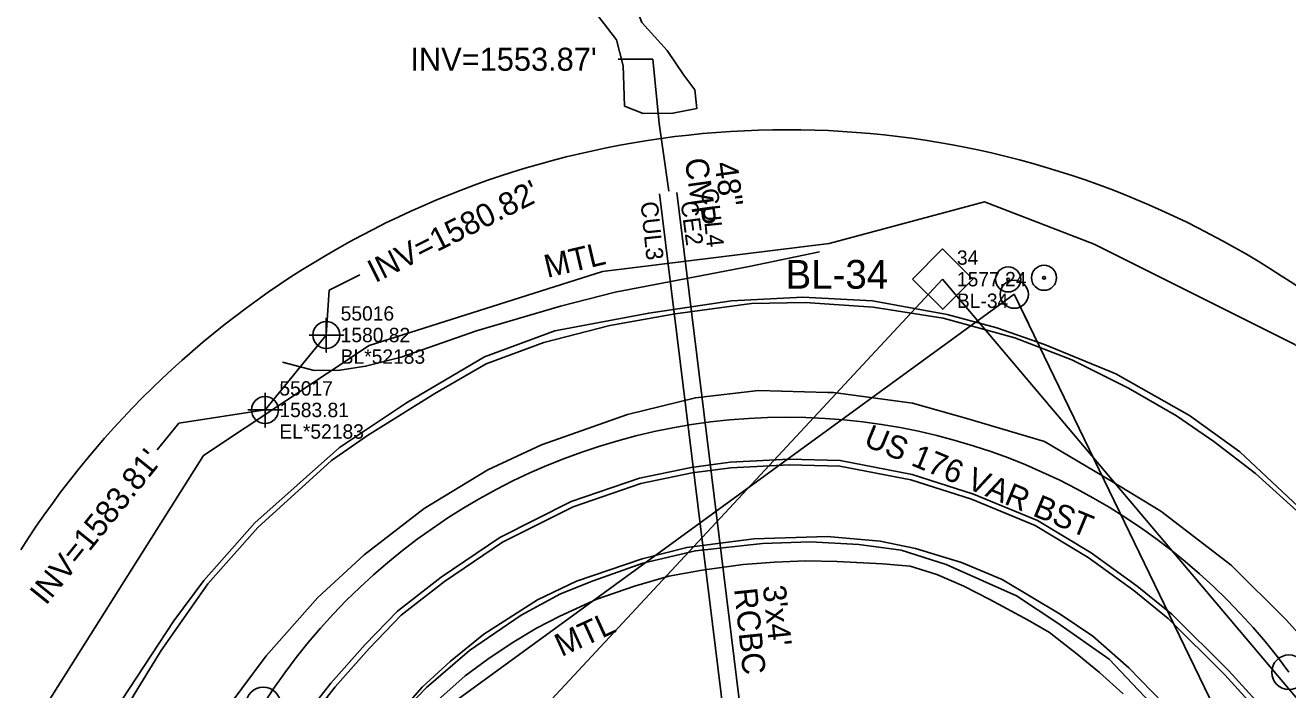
# Model space of a CAD drawing. Extents: x 1004911 to 1009660, y 551419 to 554278.
# Drawn here: x 1007382.7 to 1007602.2, y 552166.7 to 552282.2 of the extents above; entities that cross this region are included whole.
import ezdxf

# ---------------------------------------------------------------- set-up
doc = ezdxf.new("R2010")
doc.units = 0
for name, color, linetype in [('COGO Default Chain', 7, 'Continuous'), ('CTL Secondary Horizontal and Vertical CELL', 7, 'Continuous'), ('CTL Secondary Horizontal and Vertical Cogo Comment', 7, 'Continuous'), ('CTL Secondary Horizontal and Vertical Cogo Elevation', 7, 'Continuous'), ('CTL Secondary Horizontal and Vertical Cogo Number', 7, 'Continuous'), ('CTL Secondary Horizontal and Vertical Text', 7, 'Continuous'), ('Default', 7, 'Continuous'), ('Exist Guardrail Text', 7, 'Continuous'), ('Exist Horizontal Alignment', 7, 'Continuous'), ('Exist Horizontal Alignment Point', 7, 'Continuous'), ('Exist Hydro Jurisdictional Stream or Body of Water', 7, 'Continuous'), ('Exist Right of Way Line', 7, 'Continuous'), ('Exist Roads EOP Text', 7, 'Continuous'), ('Exist Roads EOT', 7, 'Continuous'), ('Exist Roads Soil', 7, 'Continuous'), ('Exist Structure Major Deck Tunnel Box Culvert Table CELL', 7, 'Continuous'), ('Exist Structure Major Deck Tunnel Box Culvert Text', 7, 'Continuous'), ('Exist Structure Minor Pipes CMP 18 Inch', 7, 'Continuous'), ('Exist Structure Minor Pipes CMP 18 Inch Cogo Comment', 7, 'Continuous'), ('Exist Structure Minor Pipes CMP 18 Inch Cogo Elevation', 7, 'Continuous'), ('Exist Structure Minor Pipes CMP 18 Inch Cogo Number', 7, 'Continuous'), ('Exist Structure Minor Pipes CMP 18 Inch Cogo Point CELL', 7, 'Continuous'), ('Exist Structure Minor Pipes CMP 18 Inch Invert', 7, 'Continuous'), ('Exist Structure Minor Pipes CMP 18 Inch Leader', 7, 'Continuous'), ('Exist Structure Minor Pipes CMP 48 Inch', 7, 'Continuous'), ('Exist Structure Minor Pipes CMP 48 Inch Invert', 7, 'Continuous'), ('Exist Structure Minor Pipes CMP 48 Inch Leader', 7, 'Continuous'), ('Exist Structure Minor Pipes CMP 48 Inch Text', 7, 'Continuous'), ('Prop Grid Mask', 7, 'Continuous'), ('Sheet Plan Layout CELL', 7, 'Continuous'), ('Sheet Plot Border Inside CELL', 7, 'Continuous')]:
    doc.layers.add(name, color=color, linetype=linetype)

msp = doc.modelspace()

# ---------------------------------------------------------------- linework, layer by layer
at = {"layer": 'COGO Default Chain'}
for p, q in [((1007359.18, 552041.29), (1007542.18, 552238.06)), ((1007542.18, 552238.06), (1007776.37, 551961.08))]:
    msp.add_line(p, q, dxfattribs=at)
at = {"layer": 'CTL Secondary Horizontal and Vertical CELL'}
msp.add_line((1007542.18, 552238.06), (1007542.18, 552238.06), dxfattribs=at)
msp.add_lwpolyline([(1007536.96, 552238.08), (1007542.2, 552243.32), (1007547.45, 552238.07), (1007542.21, 552232.83)], close=True, dxfattribs=at)
at = {"layer": 'Default'}
msp.add_lwpolyline([(1005524.55, 552120.23), (1005736, 552138.07), (1005876.82, 552290.73), (1006051.03, 552232.37), (1006285.21, 552359.76), (1006537.01, 552607.23), (1006619.79, 552246.45), (1006777.44, 552223.19), (1007040.23, 552379.15), (1007196.11, 552162.94), (1007285.57, 552039.61), (1007554.65, 552235.44), (1007625.93, 552087.97), (1007798.71, 551946.8), (1008114.55, 551869.88), (1008306.5, 551776.16), (1008516.03, 551764.25), (1008753.59, 551928.05), (1008927.98, 552049.02)], dxfattribs=at)
at = {"layer": 'Exist Horizontal Alignment'}
msp.add_arc((1007515.15, 552106.05), 108, 36.1169, 147.4703, dxfattribs=at)
at = {"layer": 'Exist Horizontal Alignment Point'}
msp.add_line((1007599.97, 552167.94), (1007599.97, 552167.94), dxfattribs=at)
for centre in [(1007602.4, 552169.71), (1007424.1, 552164.12)]:
    msp.add_circle(centre, 3, dxfattribs=at)
at = {"layer": 'Exist Hydro Jurisdictional Stream or Body of Water'}
for q in [(1007557.12, 552230.38), (1007554.65, 552235.44)]:
    msp.add_line((1007554.65, 552235.44), q, dxfattribs=at)
msp.add_lwpolyline([(1007473.32, 552313.51), (1007473.47, 552304.27), (1007474.76, 552295.25), (1007477.98, 552290.52), (1007482.38, 552283.75), (1007485.5, 552279.67), (1007486.68, 552275.16), (1007486.79, 552271.72), (1007486.9, 552268.17), (1007490.12, 552266.89), (1007495.32, 552266.91), (1007499.47, 552267.74), (1007499.14, 552270.97), (1007497.21, 552273.55), (1007494.31, 552277.84), (1007489.9, 552282.68), (1007487.22, 552289.66), (1007484.75, 552294.49), (1007482.6, 552299.65), (1007482.49, 552305.02), (1007481.29, 552315)], dxfattribs=at)
msp.add_circle((1007554.65, 552235.44), 2.45, dxfattribs=at)
at = {"layer": 'Exist Right of Way Line'}
msp.add_arc((1007515.15, 552106.05), 158, 36.1169, 147.4703, dxfattribs=at)
at = {"layer": 'Exist Roads EOT'}
for points in [[(1007604.41, 552197.18), (1007596.57, 552204.24), (1007589.34, 552209.81), (1007582.84, 552214.31), (1007574.51, 552219.09), (1007564.67, 552224.04), (1007554.72, 552227.88), (1007542.27, 552231.27), (1007530.1, 552233.22), (1007518.32, 552234), (1007508.98, 552233.83), (1007495.7, 552232.05), (1007484.36, 552229.99), (1007472.85, 552227.05), (1007462.85, 552223.32), (1007453.9, 552218.2), (1007442.23, 552210.86), (1007435.95, 552206.52), (1007423.17, 552194.85), (1007414.44, 552185.11), (1007406.33, 552173.49), (1007401.66, 552165.81), (1007387.21, 552140.79), (1007379.71, 552129.5)], [(1007608.92, 552171.03), (1007601.91, 552178.81), (1007592.38, 552188.35), (1007580.13, 552197.7), (1007571.57, 552202.95), (1007559.9, 552209.86), (1007546.38, 552213.85), (1007536.94, 552216.48), (1007523.23, 552218.33), (1007522.16, 552218.33), (1007510.2, 552218.72), (1007499.21, 552217.45), (1007487.44, 552214.53), (1007472.46, 552209.28), (1007463.12, 552204.9), (1007452.04, 552198.18), (1007441.63, 552190.1), (1007433.56, 552182.71), (1007424.61, 552172.59), (1007416.15, 552161.2)], [(1007430.81, 552161.38), (1007435.87, 552167.78), (1007441.81, 552174.51), (1007447.43, 552180.35), (1007455.04, 552186.24), (1007465.21, 552193.14), (1007477.61, 552199.37), (1007489.5, 552203.48), (1007498.5, 552205.32), (1007505.28, 552206.21), (1007515.51, 552206.76), (1007524.4, 552206.54), (1007536.91, 552204.09), (1007547.58, 552200.7), (1007558.69, 552196.09), (1007568.03, 552190.47), (1007576.03, 552184.69), (1007582.04, 552179.79), (1007591.93, 552169.95), (1007600.77, 552160.27)], [(1007431.59, 552160.8), (1007436.61, 552167.16), (1007442.53, 552173.85), (1007448.08, 552179.62), (1007455.61, 552185.46), (1007465.7, 552192.3), (1007477.98, 552198.47), (1007489.76, 552202.55), (1007498.66, 552204.36), (1007505.37, 552205.24), (1007515.52, 552205.79), (1007524.3, 552205.57), (1007536.67, 552203.15), (1007547.24, 552199.79), (1007558.26, 552195.22), (1007567.5, 552189.66), (1007575.44, 552183.92), (1007581.39, 552179.07), (1007591.23, 552169.28), (1007600.02, 552159.65)], [(1007443.4, 552157.58), (1007451.73, 552167.09), (1007456.57, 552171.6), (1007462.46, 552176.33), (1007471.74, 552182.28), (1007478.52, 552185.56), (1007489.97, 552189.45), (1007497.7, 552191.4), (1007509.37, 552192.9), (1007522.1, 552193.29), (1007531.32, 552192.51), (1007537.49, 552191.23), (1007545.49, 552188.78), (1007552.55, 552185.84), (1007562.61, 552179.83), (1007568.28, 552175.99), (1007574.56, 552170.49), (1007580.67, 552164.2)]]:
    msp.add_lwpolyline(points, dxfattribs=at)
for centre, radius in [((1007553.59, 552238.02), 2.18), ((1007559.82, 552238.3), 2.18), ((1007553.59, 552238.02), 0.24), ((1007559.82, 552238.3), 0.24)]:
    msp.add_circle(centre, radius, dxfattribs=at)
at = {"layer": 'Exist Roads Soil'}
for p, q in [((1007505.32, 552152.68), (1007492.98, 552252.9)), ((1007508.28, 552153.01), (1007495.97, 552253.15))]:
    msp.add_line(p, q, dxfattribs=at)
at = {"layer": 'Exist Structure Minor Pipes CMP 18 Inch'}
msp.add_line((1007435.05, 552228.35), (1007424.4, 552215.32), dxfattribs=at)
at = {"layer": 'Exist Structure Minor Pipes CMP 18 Inch Cogo Point CELL'}
for points in [[(1007435.05, 552231.35), (1007435.05, 552225.35), (1007435.05, 552228.35), (1007438.05, 552228.35), (1007432.05, 552228.35)], [(1007424.4, 552218.32), (1007424.4, 552212.32), (1007424.4, 552215.32), (1007427.4, 552215.32), (1007421.4, 552215.32)]]:
    msp.add_lwpolyline(points, dxfattribs=at)
for centre in [(1007435.05, 552228.35), (1007424.4, 552215.32)]:
    msp.add_circle(centre, 2.34, dxfattribs=at)
at = {"layer": 'Exist Structure Minor Pipes CMP 18 Inch Leader'}
for points in [[(1007435.05, 552228.35), (1007435.55, 552236.12), (1007440.91, 552238.82)], [(1007424.4, 552215.32), (1007409.44, 552213.03), (1007405.67, 552208.36)]]:
    msp.add_lwpolyline(points, dxfattribs=at)
at = {"layer": 'Exist Structure Minor Pipes CMP 48 Inch'}
msp.add_line((1007494.57, 552253.38), (1007492.92, 552265.15), dxfattribs=at)
at = {"layer": 'Exist Structure Minor Pipes CMP 48 Inch Leader'}
msp.add_lwpolyline([(1007492.92, 552265.15), (1007491.81, 552276.3), (1007485.81, 552276.3)], dxfattribs=at)
at = {"layer": 'Prop Grid Mask'}
for points in [[(1007427.42, 552223.6), (1007432.93, 552222.15), (1007437.43, 552222.26), (1007441.87, 552222.93), (1007448.04, 552224.49), (1007461.16, 552229.1), (1007475.78, 552233.39), (1007485.28, 552235.78), (1007508.57, 552240.28), (1007520.79, 552242.79)], [(1007573.59, 552165.94), (1007569.45, 552169.64), (1007565.57, 552172.85), (1007560.76, 552176.6), (1007557.05, 552178.77), (1007550.41, 552182.37), (1007545.86, 552184.68), (1007541.16, 552186.71), (1007536.53, 552188.15), (1007531.77, 552188.56), (1007523.84, 552188.96), (1007518.33, 552189.11), (1007512.99, 552188.87), (1007507.53, 552188.45), (1007500.41, 552187.44), (1007494.61, 552186.4), (1007488.64, 552184.69), (1007482.1, 552182.39), (1007475.64, 552179.48), (1007471.58, 552177.38), (1007467.37, 552174.82), (1007463.16, 552171.98), (1007459.22, 552169.08), (1007454.43, 552164.85)]]:
    msp.add_lwpolyline(points, dxfattribs=at)
at = {"layer": 'Sheet Plan Layout CELL'}
for points in [[(1007604.06, 552198.45), (1007593.88, 552208.01), (1007585.11, 552214.36), (1007572.29, 552221.57), (1007559.88, 552226.69), (1007551.62, 552229.58), (1007542.96, 552231.89), (1007529.98, 552234.31), (1007517.88, 552234.91), (1007505.5, 552234.31), (1007491.12, 552232.15), (1007474.81, 552229.1), (1007462.54, 552224.57), (1007448.98, 552216.57), (1007437.32, 552208.79), (1007422.65, 552195.67), (1007413.76, 552185.66), (1007408.54, 552178.66), (1007396.93, 552160.92), (1007385.26, 552139.47), (1007378.38, 552129.07)], [(1007448.06, 552162.45), (1007452.49, 552167.06), (1007459.93, 552173.48), (1007468.92, 552179.62), (1007475.76, 552183.32), (1007481.44, 552185.59), (1007490.06, 552188.67), (1007499.22, 552190.83), (1007510.86, 552192.12), (1007519.21, 552192.41), (1007527.64, 552191.9), (1007535, 552190.94), (1007542.82, 552188.44), (1007555.05, 552183.01), (1007562.07, 552178.35), (1007571.16, 552171.97), (1007580.3, 552162.32)]]:
    msp.add_lwpolyline(points, dxfattribs=at)
at = {"layer": 'Sheet Plot Border Inside CELL'}
msp.add_lwpolyline([(1008018.93, 551905.44), (1007985.96, 551910.69), (1007970.5, 551948.55), (1007944.43, 551944.76), (1007935.18, 551975.26), (1007927.71, 551982.4), (1007894.05, 551968.8), (1007853.66, 551980.36), (1007841.09, 551991.4), (1007816.34, 552003.15), (1007758.29, 552047.11), (1007642.78, 552183.47), (1007603.4, 552226.7), (1007568.56, 552244.13), (1007549.47, 552251.53), (1007522.45, 552244.25), (1007483.06, 552239.39), (1007442.5, 552226.54), (1007413.71, 552207.37), (1007375.88, 552147.49)], dxfattribs=at)

# ---------------------------------------------------------------- texts
at = {"layer": 'CTL Secondary Horizontal and Vertical Cogo Comment'}
msp.add_text('BL-34', height=2.5, dxfattribs=at).set_placement((1007544.68, 552233.06))
at = {"layer": 'CTL Secondary Horizontal and Vertical Cogo Elevation'}
msp.add_text('1577.24', height=2.5, dxfattribs=at).set_placement((1007544.68, 552236.81))
at = {"layer": 'CTL Secondary Horizontal and Vertical Cogo Number'}
msp.add_text('34', height=2.5, dxfattribs=at).set_placement((1007544.68, 552240.56))
at = {"layer": 'CTL Secondary Horizontal and Vertical Text'}
msp.add_text('BL-34', height=5, dxfattribs=at).set_placement((1007514.88, 552236.4))
at = {"layer": 'Exist Guardrail Text'}
for rotation, p in [(13.3119, (1007473.46, 552238.26)), (24.6254, (1007475.94, 552172.34))]:
    msp.add_text('MTL', height=4, rotation=rotation, dxfattribs=at).set_placement(p)
at = {"layer": 'Exist Roads EOP Text'}
msp.add_text('US 176 VAR BST ', height=4, rotation=337.464, dxfattribs=at).set_placement((1007528.27, 552209.19))
at = {"layer": 'Exist Structure Major Deck Tunnel Box Culvert Table CELL'}
for s, rotation, p in [('CUL4', 275.984, (1007500.17, 552253.71)), ('CUL3', 275.984, (1007489.67, 552251.43)), ('CE2', 277.5358, (1007496.63, 552251.48))]:
    msp.add_text(s, height=3, rotation=rotation, dxfattribs=at).set_placement(p)
at = {"layer": 'Exist Structure Major Deck Tunnel Box Culvert Text'}
for s, p in [('RCBC', (1007505.94, 552184.19)), ("3'x4'", (1007510.92, 552184.67))]:
    msp.add_text(s, height=4, rotation=275.9227, dxfattribs=at).set_placement(p)
at = {"layer": 'Exist Structure Minor Pipes CMP 18 Inch Cogo Comment'}
for s, p in [('BL*52183', (1007437.55, 552223.35)), ('EL*52183', (1007426.9, 552210.32))]:
    msp.add_text(s, height=2.5, dxfattribs=at).set_placement(p)
at = {"layer": 'Exist Structure Minor Pipes CMP 18 Inch Cogo Elevation'}
for s, p in [('1580.82', (1007437.55, 552227.1)), ('1583.81', (1007426.9, 552214.07))]:
    msp.add_text(s, height=2.5, dxfattribs=at).set_placement(p)
at = {"layer": 'Exist Structure Minor Pipes CMP 18 Inch Cogo Number'}
for s, p in [('55016', (1007437.55, 552230.85)), ('55017', (1007426.9, 552217.82))]:
    msp.add_text(s, height=2.5, dxfattribs=at).set_placement(p)
at = {"layer": 'Exist Structure Minor Pipes CMP 18 Inch Invert'}
for s, rotation, p in [("INV=1580.82'", 26.6772, (1007443.54, 552237.35)), ("INV=1583.81'", 51.1326, (1007386.31, 552181.2))]:
    msp.add_text(s, height=4, rotation=rotation, dxfattribs=at).set_placement(p)
at = {"layer": 'Exist Structure Minor Pipes CMP 48 Inch Invert'}
msp.add_text("INV=1553.87'", height=4, dxfattribs=at).set_placement((1007449.67, 552274.3))
at = {"layer": 'Exist Structure Minor Pipes CMP 48 Inch Text'}
for s, p in [('CMP', (1007497.36, 552258.88)), ('48"', (1007502.51, 552258.23))]:
    msp.add_text(s, height=4, rotation=277.9509, dxfattribs=at).set_placement(p)

doc.saveas('drawing.dxf')
